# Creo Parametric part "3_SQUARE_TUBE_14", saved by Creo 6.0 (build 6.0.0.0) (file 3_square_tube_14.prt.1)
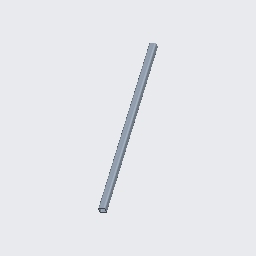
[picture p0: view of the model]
Units: Custom; MM, KILOGRAM, SECS
Materials in the file: STEEL

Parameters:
  BUW_NAME = "SQUARE TUBE"
  BUW_TYPE = "DIN EN 10219"
  BUW_SIZE = "25x25x3.0"
  BUW_LENGTH_STR = "680"
  PTC_MATERIAL_NAME = "STEEL"
  BUW_PROFIL_TYPE = "square_tube"
  BUW_PROFILE_PATH = "parts//profiles/steel_beams_mm/"
  BUW_PROFILE_NAME_LANG = "SQUARE TUBE"
  BUW_TAB_SEL_INFO = "-2 TYPE DIN_EN_10219-1997 SIZE_DINEN_10219 25x25x3.0"
  NAMING = "SQUARE TUBE"
  DESIGNATION = "DIN EN 10219 25x25x3.0 x 680"
  PROFIL_RASTER_POS = "X_0"
  BUW_OBJECT_ROLE = "PROFIL_SYSTEM_BORE_END_POINTS"
  PRO_UNIT_SYS = "Custom"

Other parameters: BUW_LENGTH, LENGTH, BUW_LENGTH_Z_MIN_PARAM, D8, D93, D94, d26, d8, d93, d94, d98, D98, SHEAR_MODULUS, THERM_EXPANSION_REF_TEMPERATURE, STRUCTURAL_DAMPING_COEFFICIENT, STRESS_LIMIT_FOR_TENSION, STRESS_LIMIT_FOR_COMPRESSION, STRESS_LIMIT_FOR_SHEAR, EMISSIVITY

Created from: SQUARE_TUBE.PRT

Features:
  1. datum plane "YZ"
  2. datum plane "XZ"
  3. datum plane "XY"
  4. coordinate system
  5. coordinate system
  6. coordinate system
  7. coordinate system
  8. datum plane "DTM3"
  9. datum plane "DTM4"
  10. datum plane "DTM5"
  11. protrusion
  12. round
  13. round
  14. datum axis
  15. datum point "PNT0"
  16. datum point

Other named items: PROFIL_CUT_QUILT, PROFILE_LENGTH_DIM, CONTACT_SURF_3, CONTACT_SURF_2, CONTACT_SURF_1, CONTACT_SURF_0, E, START_SURFACE, END_SURFACE, SIDE_SURF_3, SIDE_SURF_0, SIDE_SURF_1, SIDE_SURF_2, EDGE_7_S, EDGE_7_E, EDGE_1_S, EDGE_1_E, EDGE_3_S, EDGE_3_E, EDGE_5_S, EDGE_5_E, EDGE_6_S, EDGE_4_S, EDGE_2_S, EDGE_0_S, EDGE_6_E, EDGE_4_E, EDGE_2_E, EDGE_0_E, CS0, CS_S, CS_E, CS3

Named dimensions: X_ROT_S, Y_ROT_S, Z_OFF_S, X_ROT_E, Y_ROT_E, Z_OFF_E, PC_L, BUW_LENGTH_Z_MIN, BUW_LENGTH_DIM

Layers: 00_PROFIL_DATUM, 00_PROFIL_DRW_HIDE, 00_PROFIL_END_CSYS, 00_PROFIL_GEOMETRY, 00_PROFIL_QUILT, 00_PROFIL_SIZE_NOTE

Surfaces: 16 plane, 12 cylinder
